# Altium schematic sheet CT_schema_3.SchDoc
size 258 x 142 mm
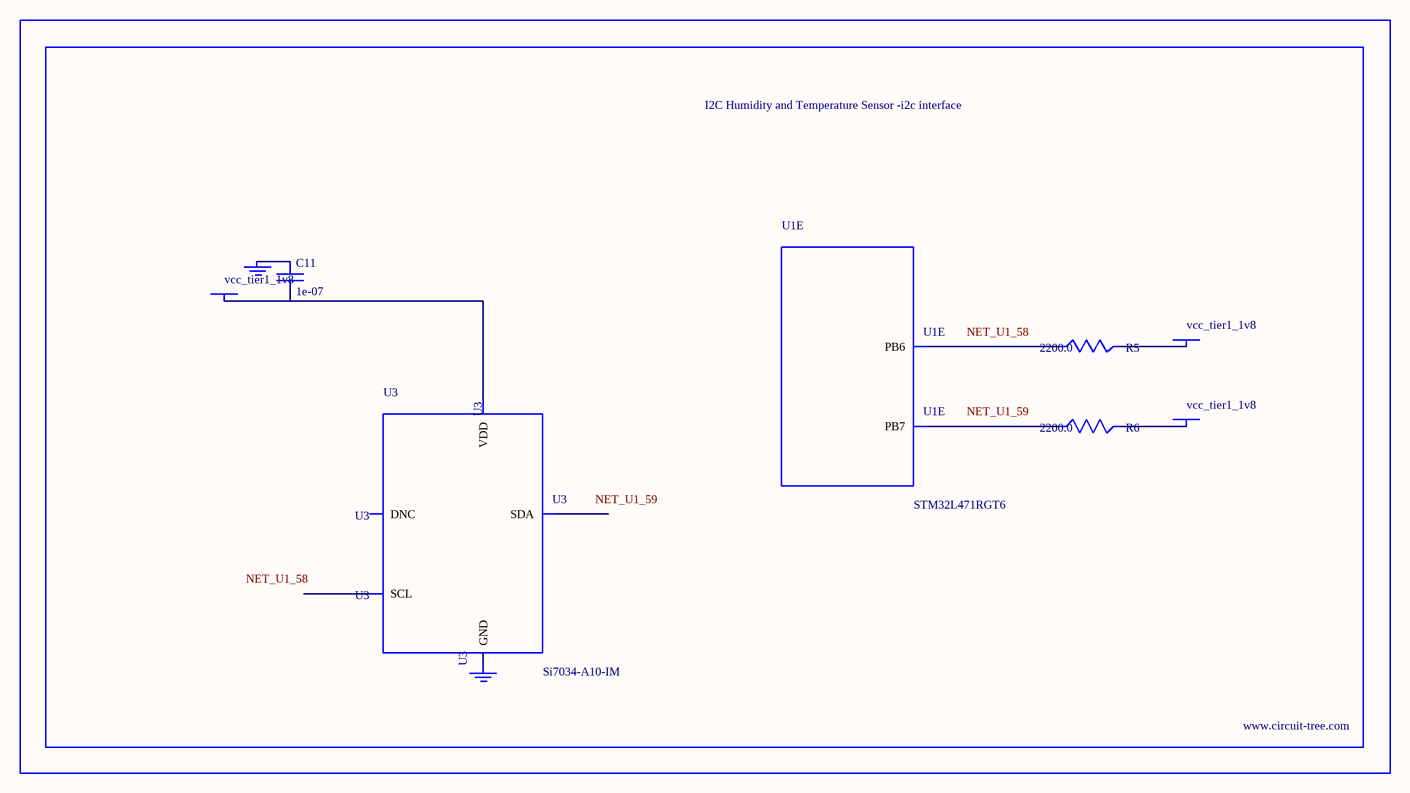
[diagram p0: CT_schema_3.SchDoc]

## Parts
BORDER2  (no value)
C11  1e-07  [C0402]
GND_INSTANCE_2_0  (no value)
GND_INSTANCE_2_1  (no value)
POWER_INSTANCE_2_0  vcc_tier1_1v8
POWER_INSTANCE_2_1  vcc_tier1_1v8
POWER_INSTANCE_2_2  vcc_tier1_1v8
R5  2200.0  [R0603]
R6  2200.0  [R0603]
U1  STM32L471RGT6  [LQFP64]  (part E of 6)
U3  Si7034-A10-IM  [SI7034-A10-IM]

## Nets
NetC11_1: C11.1 GND_INSTANCE_2_0.0(GND)
NetC11_2: C11.2 POWER_INSTANCE_2_0.0(PWR) U3.1(VDD)
NetGND_INSTANCE_2_1_0: GND_INSTANCE_2_1.0(GND) U3.5(GND)
NetPOWER_INSTANCE_2_1_0: POWER_INSTANCE_2_1.0(PWR) R5.2
NetPOWER_INSTANCE_2_2_0: POWER_INSTANCE_2_2.0(PWR) R6.2
NetR5_1: R5.1 U1.58(PB6)
NetR6_1: R6.1 U1.59(PB7)

Not connected (* = marked no-connect by the designer): U3 2(SCL) 3(DNC) 4(SDA)

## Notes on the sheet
- Labels drawn without touching a wire or pin: NET_U1_58, NET_U1_59

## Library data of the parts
BORDER2 = BORDER_PAGE2
C11 = C0402C104K3RACTU
GND_INSTANCE_2_0 GND_INSTANCE_2_1 = GND
POWER_INSTANCE_2_0-POWER_INSTANCE_2_2 = PWR
R5 R6 = RC0603JR-072K2L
